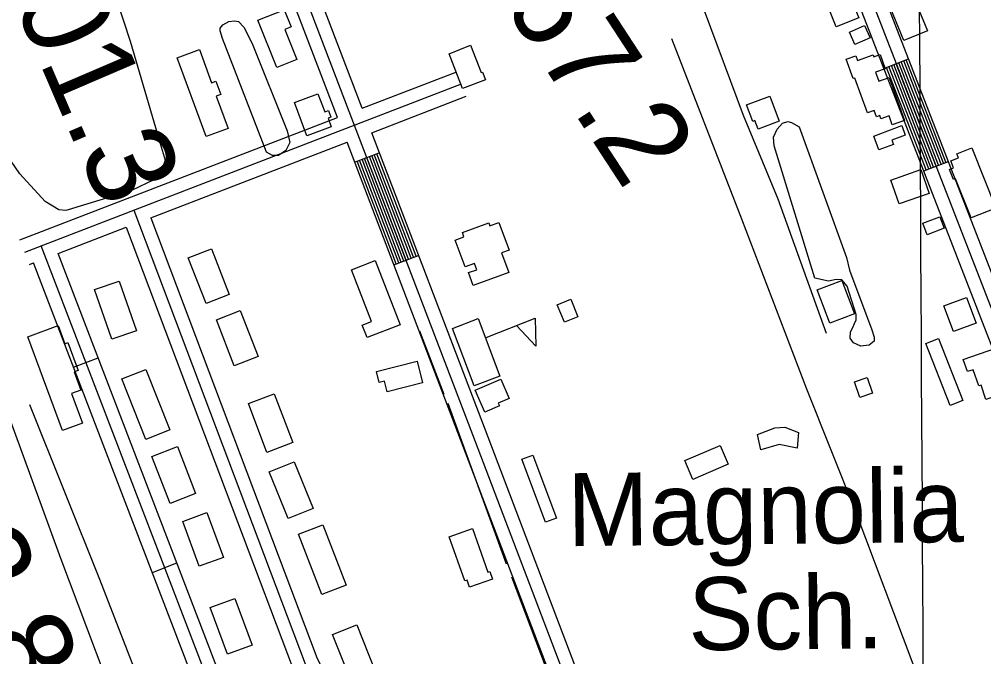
# Model space of a CAD drawing. Extents: x 3445503 to 3483459, y 540493 to 566012.
# Drawn here: x 3474986 to 3476082, y 548542 to 549267 of the extents above; entities that cross this region are included whole.
import ezdxf

# ---------------------------------------------------------------- set-up
doc = ezdxf.new("R2010")
doc.units = 0
for name, color, linetype in [('V-BLDG-IDEN', 7, 'Continuous'), ('V-BLDG-OTLN', 7, 'Continuous'), ('V-GRID-MAJR', 7, 'Continuous'), ('V-ROAD-CNTR', 7, 'Continuous'), ('V-SITE-VEGE', 7, 'Continuous'), ('V-SURV-IDEN', 7, 'Continuous'), ('V-TOPO-SHOR', 7, 'Continuous')]:
    doc.layers.add(name, color=color, linetype=linetype)

msp = doc.modelspace()

# ---------------------------------------------------------------- linework, layer by layer
at = {"layer": 'V-BLDG-OTLN'}
msp.add_line((3475516.4, 548904.8), (3475572.1, 548927.1), dxfattribs=at)
for points in [[(3475984, 549336.9), (3476018.1, 549253.6), (3475991.2, 549242.6), (3475969.4, 549295.9), (3475965.8, 549294.4), (3475960.4, 549307.6), (3475964.4, 549309.3), (3475957.5, 549326)], [(3475914.3, 549258.4), (3475898.1, 549298.6), (3475922.9, 549308.6), (3475926.5, 549299.5), (3475931.9, 549301.7), (3475937.1, 549288.7), (3475932.5, 549286.9), (3475939.9, 549268.7)], [(3475278.3, 549212.1), (3475256.8, 549265.8), (3475286.6, 549277.8), (3475294.5, 549258.3), (3475287.3, 549255.4), (3475301, 549221.2)], [(3475952.6, 549245.7), (3475935.5, 549238.1), (3475929.2, 549252.1), (3475946.3, 549259.8)], [(3475498.5, 549237.3), (3475510.6, 549206.3), (3475512.1, 549206.9), (3475515.6, 549198.2), (3475489.6, 549188), (3475474.1, 549227.7)], [(3475197.9, 549133.6), (3475165.2, 549223.2), (3475190.5, 549232.4), (3475204.2, 549194.7), (3475209.1, 549196.5), (3475214.7, 549181.3), (3475209.5, 549179.4), (3475222.9, 549142.7)], [(3475974.4, 549200.7), (3475991.9, 549151.7), (3475977.9, 549146.7), (3475974.2, 549156.9), (3475965, 549153.6), (3475963.6, 549157.3), (3475960.1, 549156), (3475957.5, 549163.2), (3475949.7, 549160.4), (3475935.5, 549200.1), (3475933.4, 549199.4), (3475925.6, 549221.4), (3475936.5, 549225.2), (3475938.4, 549219.9), (3475956.1, 549226.3), (3475956.9, 549224.1), (3475964.2, 549226.7), (3475969.9, 549210.7), (3475958.8, 549206.8), (3475962.5, 549196.5)], [(3475340.3, 549144.7), (3475312.6, 549134.4), (3475298.5, 549172.1), (3475325.1, 549182), (3475332.8, 549161.5), (3475337.1, 549163.1), (3475339.9, 549155.6), (3475336.7, 549154.4)], [(3475812.4, 549169.4), (3475838.8, 549179.3), (3475849.4, 549150.9), (3475825.3, 549141.9), (3475821.7, 549151.6), (3475819.4, 549150.7)], [(3475962.8, 549118.4), (3475957, 549134.1), (3475988.8, 549145.9), (3475992.7, 549135.2), (3475977.5, 549129.5), (3475979.3, 549124.5)], [(3476095.8, 549052.2), (3476067.6, 549040.9), (3476049.9, 549085.5), (3476047.5, 549084.6), (3476042.9, 549096), (3476047.5, 549097.8), (3476044.3, 549105.7), (3476053.1, 549109.2), (3476051.2, 549114), (3476068.5, 549120.8)], [(3475976.1, 549084), (3476010.2, 549096.1), (3476019.9, 549068.9), (3475985.7, 549056.8)], [(3476037, 549029.4), (3476017.5, 549021.9), (3476012.5, 549034.9), (3476032.1, 549042.3)], [(3475492.4, 548985.2), (3475481.2, 549015.7), (3475491.1, 549019.3), (3475489.3, 549024.3), (3475519.3, 549035.3), (3475520.5, 549032.1), (3475530.9, 549035.9), (3475542.5, 549004.4), (3475533.6, 549001.2), (3475541.9, 548978.7), (3475501.7, 548964), (3475496.3, 548978.7), (3475505.6, 548982.1), (3475503, 548989.1)], [(3475198, 548943.7), (3475177.8, 548995.5), (3475204.2, 549005.8), (3475224.4, 548954)], [(3475390.2, 548992.4), (3475418.5, 548919.3), (3475381, 548904.8), (3475375.5, 548918.9), (3475386, 548923), (3475363.2, 548981.9)], [(3475099.1, 548969.1), (3475118.8, 548912.7), (3475091, 548903), (3475071.3, 548959.4)], [(3475920.6, 548969.6), (3475934.9, 548931.8), (3475907, 548921.2), (3475892.7, 548959)], [(3475605.3, 548922.3), (3475597.2, 548942.2), (3475612.4, 548948.4), (3475620.5, 548928.5)], [(3476047.6, 548911.8), (3476036.7, 548940.9), (3476062.3, 548950.5), (3476073.2, 548921.4)], [(3475230, 548872.8), (3475209.8, 548925.1), (3475236.8, 548935.6), (3475257, 548883.3)], [(3475502.6, 548850), (3475477.9, 548915.3), (3475507.3, 548926.4), (3475531.9, 548861.1)], [(3475572.1, 548927.1), (3475572.6, 548895), (3475550.7, 548918.5)], [(3475034.7, 548799.2), (3474995.2, 548905.7), (3475029.9, 548918.5), (3475037.5, 548897.9), (3475041, 548899.2), (3475052.7, 548867.6), (3475048, 548865.8), (3475055.6, 548845.2), (3475045.1, 548841.3), (3475057.6, 548807.7)], [(3476043.8, 548827.6), (3476016, 548898.3), (3476030.4, 548904), (3476058.2, 548833.3)], [(3476095.6, 548892.7), (3476105.4, 548864.1), (3476098.5, 548861.7), (3476105.4, 548841.7), (3476084.4, 548834.5), (3476078.8, 548850.8), (3476076.2, 548849.9), (3476069.8, 548868.3), (3476063.4, 548866.1), (3476058.6, 548880)], [(3475437.9, 548877.9), (3475444.1, 548853.4), (3475403.8, 548843.2), (3475400.7, 548855.4), (3475394.8, 548853.9), (3475391.6, 548866.2)], [(3475156.9, 548799.8), (3475129.5, 548789), (3475102.3, 548857.9), (3475129.6, 548868.7)], [(3475514.7, 548819.9), (3475503.9, 548844.9), (3475533, 548857.5), (3475542.5, 548835.6), (3475530, 548830.2), (3475531.3, 548827.1)], [(3475935, 548854.5), (3475949.3, 548859.4), (3475955.4, 548841.5), (3475941.1, 548836.6)], [(3475267.2, 548774.3), (3475246.1, 548829.8), (3475275.4, 548840.9), (3475296.5, 548785.4)], [(3475824.8, 548794.6), (3475844.5, 548802.3), (3475855.9, 548803), (3475871.2, 548796.9), (3475869.8, 548779.2), (3475849.4, 548783.4), (3475828.5, 548777.3)], [(3475165.4, 548780.8), (3475186.1, 548727.6), (3475157, 548716.3), (3475136.4, 548769.6)], [(3475791.3, 548760.7), (3475751.1, 548743.6), (3475742.1, 548764.9), (3475782.3, 548782)], [(3475583.6, 548694.8), (3475556.7, 548766.4), (3475569.4, 548771.1), (3475596.3, 548699.5)], [(3475291.3, 548698.9), (3475269.7, 548752.1), (3475298.2, 548763.6), (3475319.8, 548710.4)], [(3475198.7, 548705.8), (3475217.6, 548654.9), (3475190.2, 548644.8), (3475171.4, 548695.7)], [(3475329.6, 548612.8), (3475303.1, 548681.2), (3475330.7, 548691.9), (3475357.2, 548623.4)], [(3475492.2, 548628), (3475474.3, 548678.3), (3475500.7, 548687.7), (3475518.3, 548638), (3475520.5, 548638.8), (3475523.6, 548630.1), (3475497.5, 548620.8), (3475494.6, 548628.8)], [(3475230.5, 548608.2), (3475250.2, 548555), (3475222.5, 548544.8), (3475202.8, 548598)], [(3475362.7, 548514.2), (3475341.6, 548567), (3475369.2, 548578.1), (3475390.3, 548525.3)]]:
    msp.add_lwpolyline(points, close=True, dxfattribs=at)
at = {"layer": 'V-GRID-MAJR'}
msp.add_spline([(3476027.1, 546019.5), (3475994.4, 552078.6), (3475961.8, 558139.5), (3475929.2, 564200.5), (3475929.2, 564202.4)], degree=3, dxfattribs=at)
at = {"layer": 'V-ROAD-CNTR'}
for p, q in [((3475968.5, 549211), (3475996.5, 549221.8)), ((3475366.8, 549104.4), (3475394.8, 549115.1)), ((3476013.8, 549094.4), (3476041.7, 549105.3)), ((3475411.4, 548987.6), (3475439.5, 548998.3)), ((3475047.4, 548871.3), (3475075.4, 548882)), ((3475136.9, 548637.8), (3475164.9, 548648.6))]:
    msp.add_line(p, q, dxfattribs=at)
for points in [[(3475542.4, 550367.6), (3475757.9, 549794.6), (3476120.4, 548861.3), (3476493.9, 547886.3)], [(3476490, 547938.4), (3476134.4, 548866.7), (3475771.9, 549799.9), (3475556.5, 550372.8)], [(3476479.9, 547881), (3476106.4, 548855.9), (3475743.9, 549789.2), (3475528.4, 550362.3)], [(3475375.3, 550248.8), (3475398.5, 550214.6), (3475416.8, 550181.9), (3475441.8, 550117.2), (3475487.6, 549990.8), (3475539.4, 549850.4), (3475604.3, 549692.5), (3475641.4, 549600.1), (3475704.8, 549437.4), (3475762.1, 549283.8), (3475764.1, 549276.9), (3475808.5, 549158), (3475847.7, 549062.8), (3475902.9, 548909.9)], [(3475375.4, 549165.9), (3475191.3, 549647.6), (3475186, 549669.9), (3475182.1, 549691.1), (3475180.2, 549724.7), (3475179.6, 549752.8), (3475178.4, 549786.5), (3475171.9, 549816.8), (3475161.6, 549847.6), (3475074.7, 550061)], [(3475347.4, 549155.1), (3475162.6, 549638.7), (3475156.6, 549663.6), (3475152.2, 549687.5), (3475150.2, 549723.5), (3475149.6, 549751.9), (3475148.5, 549782.8), (3475143, 549808.9), (3475133.5, 549837.2), (3475046.9, 550049.7)], [(3476552.1, 546025.4), (3476203.6, 546933.7), (3475839.4, 547905.3), (3475501.3, 548794.4), (3475177, 549643.2), (3475171.3, 549666.7), (3475167.1, 549689.3), (3475165.2, 549724.1), (3475164.6, 549752.3), (3475163.4, 549784.7), (3475157.4, 549812.8), (3475147.6, 549842.4), (3475060.8, 550055.4)], [(3476027.7, 549099.9), (3475982.5, 549216.4)], [(3476030.5, 549101), (3475985.3, 549217.5)], [(3476033.3, 549102), (3475988.1, 549218.6)], [(3476036.1, 549103.1), (3475990.9, 549219.6)], [(3476038.9, 549104.2), (3475993.7, 549220.7)], [(3475375.4, 549165.9), (3475482.9, 549207.3)], [(3476016.6, 549095.5), (3475971.3, 549212)], [(3476019.4, 549096.6), (3475974.1, 549213.1)], [(3476022.2, 549097.7), (3475976.9, 549214.2)], [(3476024.9, 549098.8), (3475979.7, 549215.3)], [(3474991.8, 549002), (3475488.3, 549193.3)], [(3475386.2, 549137.8), (3475493.7, 549179.3)], [(3474986.4, 549016), (3475347.4, 549155.1)], [(3475663.4, 548410.4), (3475515.4, 548799.7), (3475386.2, 549137.8)], [(3475135.1, 549041.1), (3475358.2, 549127.1)], [(3476536.1, 546025.3), (3476189.5, 546928.3), (3475825.3, 547900), (3475487.3, 548789), (3475358.2, 549127.1)], [(3475417, 548989.8), (3475372.4, 549106.5)], [(3475419.8, 548990.8), (3475375.2, 549107.6)], [(3475422.6, 548991.9), (3475378, 549108.7)], [(3475425.4, 548993), (3475380.8, 549109.8)], [(3475428.2, 548994.1), (3475383.6, 549110.8)], [(3475431.1, 548995.1), (3475386.4, 549111.9)], [(3475433.9, 548996.2), (3475389.2, 549113)], [(3475436.7, 548997.3), (3475392, 549114)], [(3475414.2, 548988.7), (3475369.6, 549105.5)], [(3475115.8, 549049.8), (3475310.6, 548533.8), (3475318.6, 548517.9), (3475326, 548507.7), (3475337.9, 548496), (3475395.1, 548441.5), (3475419.2, 548420.4), (3475434.3, 548399.7), (3475453.2, 548372.4), (3475470, 548335.1), (3475480.3, 548306.3), (3475486.7, 548285.7), (3475490.8, 548267.3), (3475492.3, 548232), (3475486.4, 548163.8), (3475485.9, 548129.4), (3475485.6, 548112.6), (3475486.4, 548091.7), (3475493.1, 548061.6), (3475585.7, 547817.5), (3475936.4, 546902)], [(3475135.1, 549041.1), (3475324.3, 548539.9), (3475331.4, 548525.7), (3475337.4, 548517.6), (3475348.3, 548506.7), (3475405.2, 548452.6), (3475430.3, 548430.6), (3475446.5, 548408.3), (3475466.3, 548379.8), (3475483.9, 548340.8), (3475494.6, 548311.1), (3475501.2, 548289.6), (3475505.8, 548269.2), (3475507.3, 548231.6), (3475501.4, 548163), (3475500.9, 548129.2), (3475500.6, 548112.8), (3475501.3, 548093.6), (3475507.5, 548065.9), (3475599.7, 547822.8), (3475945, 546921.3)], [(3475029.9, 549000.6), (3475107.1, 549030.3)], [(3475107.1, 549030.3), (3475296.8, 548527.8), (3475305.7, 548510), (3475314.6, 548497.9), (3475327.4, 548485.2), (3475384.9, 548430.4), (3475408.1, 548410.2), (3475422.1, 548391), (3475440.1, 548365), (3475456.1, 548329.5), (3475466.1, 548301.6), (3475472.2, 548281.8), (3475475.9, 548265.3), (3475477.3, 548232.3), (3475471.4, 548164.5), (3475470.9, 548129.7), (3475470.6, 548112.5), (3475471.4, 548089.8), (3475478.7, 548057.3), (3475571.7, 547812.2), (3475918, 546907.9)], [(3475702.6, 547194.7), (3475319.9, 548202.4), (3475010.5, 549009.2)], [(3475716.6, 547200), (3475333.9, 548207.8), (3475029.9, 549000.6)], [(3474997.2, 548988), (3475001.9, 548989.8)], [(3475688.5, 547189.4), (3475305.8, 548197.1), (3475001.9, 548989.8)]]:
    msp.add_lwpolyline(points, dxfattribs=at)
at = {"layer": 'V-SITE-VEGE'}
for points in [[(3475059.2, 549403.3), (3475111.7, 549242.1), (3475147.1, 549121.8), (3475151.3, 549106.8), (3475146.8, 549093.9), (3475138.6, 549084.3), (3475113.2, 549072.2), (3475041.3, 549050.3), (3475038.6, 549049.5), (3475030.7, 549050.2), (3475014.9, 549059.8), (3474986.3, 549091.2), (3474971.7, 549112.8), (3474925.8, 549229.5), (3474906.1, 549287.7)], [(3474956.1, 548862.9), (3475032.5, 548653.9), (3475112.4, 548441.6)]]:
    msp.add_lwpolyline(points, dxfattribs=at)
for points in [[(3475224, 549264.2), (3475230.3, 549265.3), (3475234.9, 549264.3), (3475240.8, 549258), (3475250.3, 549239.5), (3475290, 549140.1), (3475293.3, 549126.9), (3475288.6, 549117.8), (3475280.3, 549112.1), (3475273.4, 549112), (3475266.5, 549115.9), (3475216.5, 549245.2), (3475213.8, 549253.9), (3475213.8, 549256.7), (3475216.9, 549260.6)], [(3475872, 549144.6), (3475925.7, 548995.8), (3475929.3, 548981.5), (3475954.6, 548913.5), (3475957.5, 548905.4), (3475957.5, 548900.8), (3475951.6, 548896.3), (3475942, 548895), (3475933.9, 548898.7), (3475930.1, 548904.1), (3475930.6, 548911.4), (3475933.2, 548916.5), (3475935.1, 548920.8), (3475936.8, 548925.2), (3475937, 548931.2), (3475926.8, 548963.3), (3475920.6, 548970.5), (3475914.2, 548971), (3475905.4, 548969), (3475890, 548972.4), (3475843.7, 549123), (3475843.1, 549132.7), (3475846.9, 549141.9), (3475853.2, 549148.7), (3475859.2, 549150.5), (3475863.5, 549149.5)]]:
    msp.add_lwpolyline(points, close=True, dxfattribs=at)
at = {"layer": 'V-TOPO-SHOR'}
for p, q in [((3475440.7, 548912.6), (3475468.2, 548840.5)), ((3475472.8, 548830.2), (3475538.9, 548647.6)), ((3475545.1, 548632.6), (3475588.7, 548517.4))]:
    msp.add_line(p, q, dxfattribs=at)
for points in [[(3476001.7, 548533.4), (3475937, 548705.7), (3475880.9, 548846.2), (3475806.8, 549039.4), (3475727.2, 549244.5)], [(3475399.9, 547810.7), (3475341.2, 547956.7), (3475271.1, 548137.4), (3475201.5, 548311.2), (3475140.1, 548467.6), (3475077.4, 548629.6), (3474997.8, 548828.4)]]:
    msp.add_lwpolyline(points, dxfattribs=at)

# ---------------------------------------------------------------- texts
at = {"layer": 'V-BLDG-IDEN'}
for s, p in [('Magnolia', (3475609, 548667.5)), ('Sch.', (3475746.4, 548549.1))]:
    msp.add_text(s, height=83, rotation=0.6418, dxfattribs=at).set_placement(p)
at = {"layer": 'V-SURV-IDEN'}
for s, rotation, p in [('1400+01.3', 293.2499, (3474830.4, 549632.3)), ('1401+67.2', 303.1347, (3475327.5, 549602.7)), ('1396+22.8', 295.4176, (3474694.6, 549068.6))]:
    msp.add_text(s, height=100, rotation=rotation, dxfattribs=at).set_placement(p)

doc.saveas('drawing.dxf')
